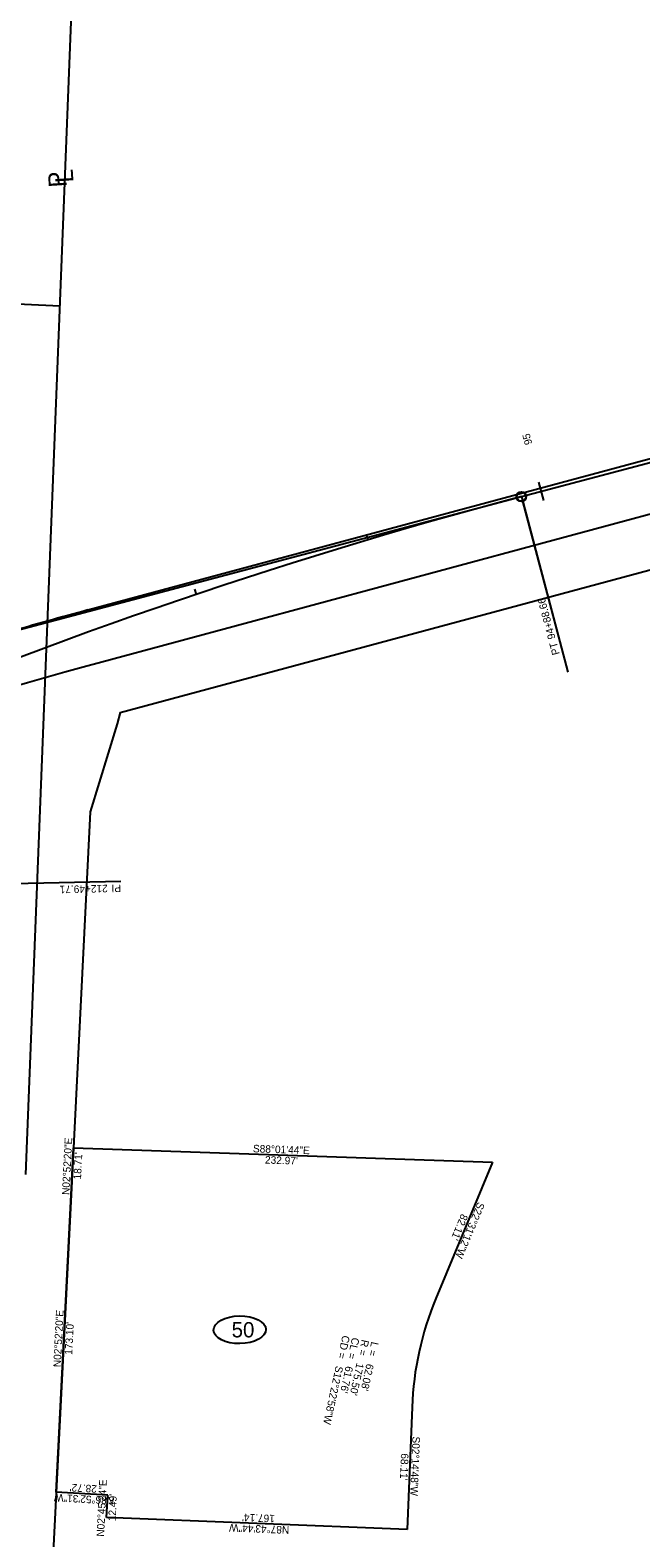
# Model space of a CAD drawing. Extents: x 1145508 to 2262867, y -3126236 to 2021677.
# Drawn here: x 1151715 to 1152054, y 2019963 to 2020801 of the extents above; entities that cross this region are included whole.
import ezdxf

# ---------------------------------------------------------------- set-up
doc = ezdxf.new("R2010")
doc.units = 0
for name, color, linetype in [('Default', 7, 'Continuous'), ('DSN_RDWY_Alignment', 7, 'Continuous'), ('DSN_RDWY_Alignment Annotation', 7, 'Continuous'), ('DSN_ROW_Line-Annotation', 7, 'Continuous'), ('DSN_ROW_Prop-Line', 7, 'Continuous'), ('DSN_ROW_Prop-Line-Annotation', 7, 'Continuous'), ('E_Const Align', 7, 'Continuous'), ('EX_PROPERTY', 7, 'Continuous'), ('EX_ROW', 7, 'Continuous'), ('EX_ROW_ANNOT', 7, 'Continuous'), ('EX_SECTION', 7, 'Continuous')]:
    doc.layers.add(name, color=color, linetype=linetype)

msp = doc.modelspace()

# ---------------------------------------------------------------- linework, layer by layer
at = {"layer": 'Default'}
msp.add_line((1152927.5, 2020766.16), (1151754.96, 2020449.8), dxfattribs=at)
msp.add_arc((1152351.97, 2018237.09), 2291.83, 105.0994, 122.23857, dxfattribs=at)
at = {"layer": 'DSN_RDWY_Alignment'}
msp.add_line((1151636.3, 2020448.46), (1151988, 2020541.79), dxfattribs=at)
msp.add_lwpolyline([(1151988, 2020541.79), (1152013.9, 2020444.21)], dxfattribs=at)
msp.add_circle((1151988, 2020541.79), 2.5, dxfattribs=at)
at = {"layer": 'DSN_RDWY_Alignment Annotation'}
for p, q in [((1151997.6, 2020549.86), (1152000.32, 2020539.6)), ((1151988, 2020541.79), (1151988, 2020541.79)), ((1151988.69, 2020539.21), (1152011.09, 2020454.8)), ((1151901.82, 2020520.6), (1151902.68, 2020517.73)), ((1151806.42, 2020490.28), (1151807.38, 2020487.44)), ((1152011.09, 2020454.8), (1152011.09, 2020454.8)), ((1151705.52, 2020326.67), (1151765.5, 2020327.9)), ((1151765.5, 2020327.9), (1151765.5, 2020327.9))]:
    msp.add_line(p, q, dxfattribs=at)
msp.add_circle((1151988, 2020541.79), 2.67, dxfattribs=at)
at = {"layer": 'DSN_ROW_Line-Annotation'}
msp.add_ellipse((1151831.53, 2020078.45), major_axis=(14.54, 0.23), ratio=0.529773, dxfattribs=at)
at = {"layer": 'DSN_ROW_Prop-Line'}
msp.add_line((1151663.71, 2020651.28), (1151731.59, 2020647.87), dxfattribs=at)
at = {"layer": 'E_Const Align'}
msp.add_line((1151988, 2020541.79), (1152894.57, 2020782.35), dxfattribs=at)
msp.add_arc((1152722.75, 2017772.83), 2864.79, 104.86102, 121.82944, dxfattribs=at)
msp.add_arc((1152722.75, 2017772.83), 2864.79, 104.86102, 121.82944, dxfattribs=at)
at = {"layer": 'EX_PROPERTY'}
for p, q in [((1151738.17, 2020161.01), (1151739.11, 2020179.7)), ((1151739.11, 2020179.7), (1151971.94, 2020171.69)), ((1151971.94, 2020171.69), (1151940.49, 2020095.84)), ((1151729.5, 2019988.13), (1151738.17, 2020161.01)), ((1151927.25, 2020035.51), (1151924.58, 2019967.46)), ((1151758.17, 2019986.55), (1151729.5, 2019988.12)), ((1151757.57, 2019974.08), (1151758.17, 2019986.55)), ((1151924.58, 2019967.46), (1151757.57, 2019974.08))]:
    msp.add_line(p, q, dxfattribs=at)
msp.add_arc((1152102.62, 2020028.63), 175.5, 157.48288, 177.75129, dxfattribs=at)
at = {"layer": 'EX_ROW'}
for p, q in [((1151747.15, 2020478.76), (1152919.68, 2020795.12)), ((1151765.09, 2020421.72), (1152911.54, 2020730.78)), ((1151765.09, 2020421.72), (1151763.37, 2020415.46)), ((1151763.37, 2020415.46), (1151748.49, 2020366.54)), ((1151748.49, 2020366.54), (1151738.18, 2020161.01)), ((1151738.18, 2020161.01), (1151725.1, 2019900.39))]:
    msp.add_line(p, q, dxfattribs=at)
for start, end in [(105.0994, 105.67369), (105.67369, 106.8026)]:
    msp.add_arc((1152351.97, 2018237.09), 2321.83, start, end, dxfattribs=at)
at = {"layer": 'EX_SECTION'}
msp.add_line((1151712.63, 2020164.79), (1151764.37, 2021482.95), dxfattribs=at)

# ---------------------------------------------------------------- texts
at = {"layer": 'DSN_RDWY_Alignment Annotation'}
for s, rotation, p in [('95', 104.86102, (1151994.1, 2020571.22)), ('94+88.66', 104.86102, (1152007.03, 2020463.09)), ('PT', 104.86102, (1152009.35, 2020454.34)), ('212+49.71', 181.17445, (1151758.13, 2020325.95)), ('PI ', 181.17445, (1151765.54, 2020326.1))]:
    msp.add_text(s, height=4.2, rotation=rotation, dxfattribs=at).set_placement(p)
at = {"layer": 'DSN_ROW_Line-Annotation'}
msp.add_text('50', height=8.5, dxfattribs=at).set_placement((1151827.02, 2020074.24))
at = {"layer": 'DSN_ROW_Prop-Line-Annotation'}
for s, p in [('P', (1151735.49, 2020714.1)), ('L', (1151739.17, 2020716.68))]:
    msp.add_text(s, height=10, rotation=93.78824, dxfattribs=at).set_placement(p)
at = {"layer": 'EX_ROW_ANNOT'}
for s, rotation, p in [('N02°52\'20"E', 87.12776, (1151736.89, 2020153.37)), ('S88°01\'44"E', 358.02879, (1151838.81, 2020177.17)), ("18.71'", 87.12776, (1151743.33, 2020161.96)), ("232.97'", 358.02879, (1151845.5, 2020170.93)), ('S22°31\'12"W', 247.47986, (1151963.86, 2020149.83)), ("82.11'", 247.47986, (1151954.63, 2020143.25)), ('N02°52\'20"E', 87.12776, (1151732.08, 2020057.58)), ("173.10'", 87.12776, (1151738.44, 2020064.47)), ('CD = ', 257.61709, (1151888.66, 2020075.6)), ('CL = ', 257.61709, (1151893.99, 2020074.43)), ('R = ', 257.61709, (1151899.33, 2020073.26)), ('L = ', 257.61709, (1151904.66, 2020072.09)), ('S12°22\'58"W', 257.61709, (1151884.93, 2020058.63)), ("61.76'", 257.61709, (1151890.5, 2020058.54)), ("175.50'", 257.61709, (1151896.48, 2020060.29)), ("62.08'", 257.61709, (1151901.97, 2020059.85)), ('S02°14\'48"W', 267.75329, (1151927.51, 2020019.21)), ("68.11'", 267.75329, (1151921.14, 2020009.83)), ("28.72'", 176.87529, (1151752.25, 2019991.99)), ('N02°45\'24"E', 87.24336, (1151756.15, 2019963.32)), ('N86°52\'31"W', 176.87529, (1151761.82, 2019985.45)), ("12.49'", 87.24336, (1151762.57, 2019971.93)), ("167.14'", 177.72902, (1151851.13, 2019975.47)), ('N87°43\'44"W', 177.72902, (1151859.09, 2019969.15))]:
    msp.add_text(s, height=4.2, rotation=rotation, dxfattribs=at).set_placement(p)

doc.saveas('drawing.dxf')
